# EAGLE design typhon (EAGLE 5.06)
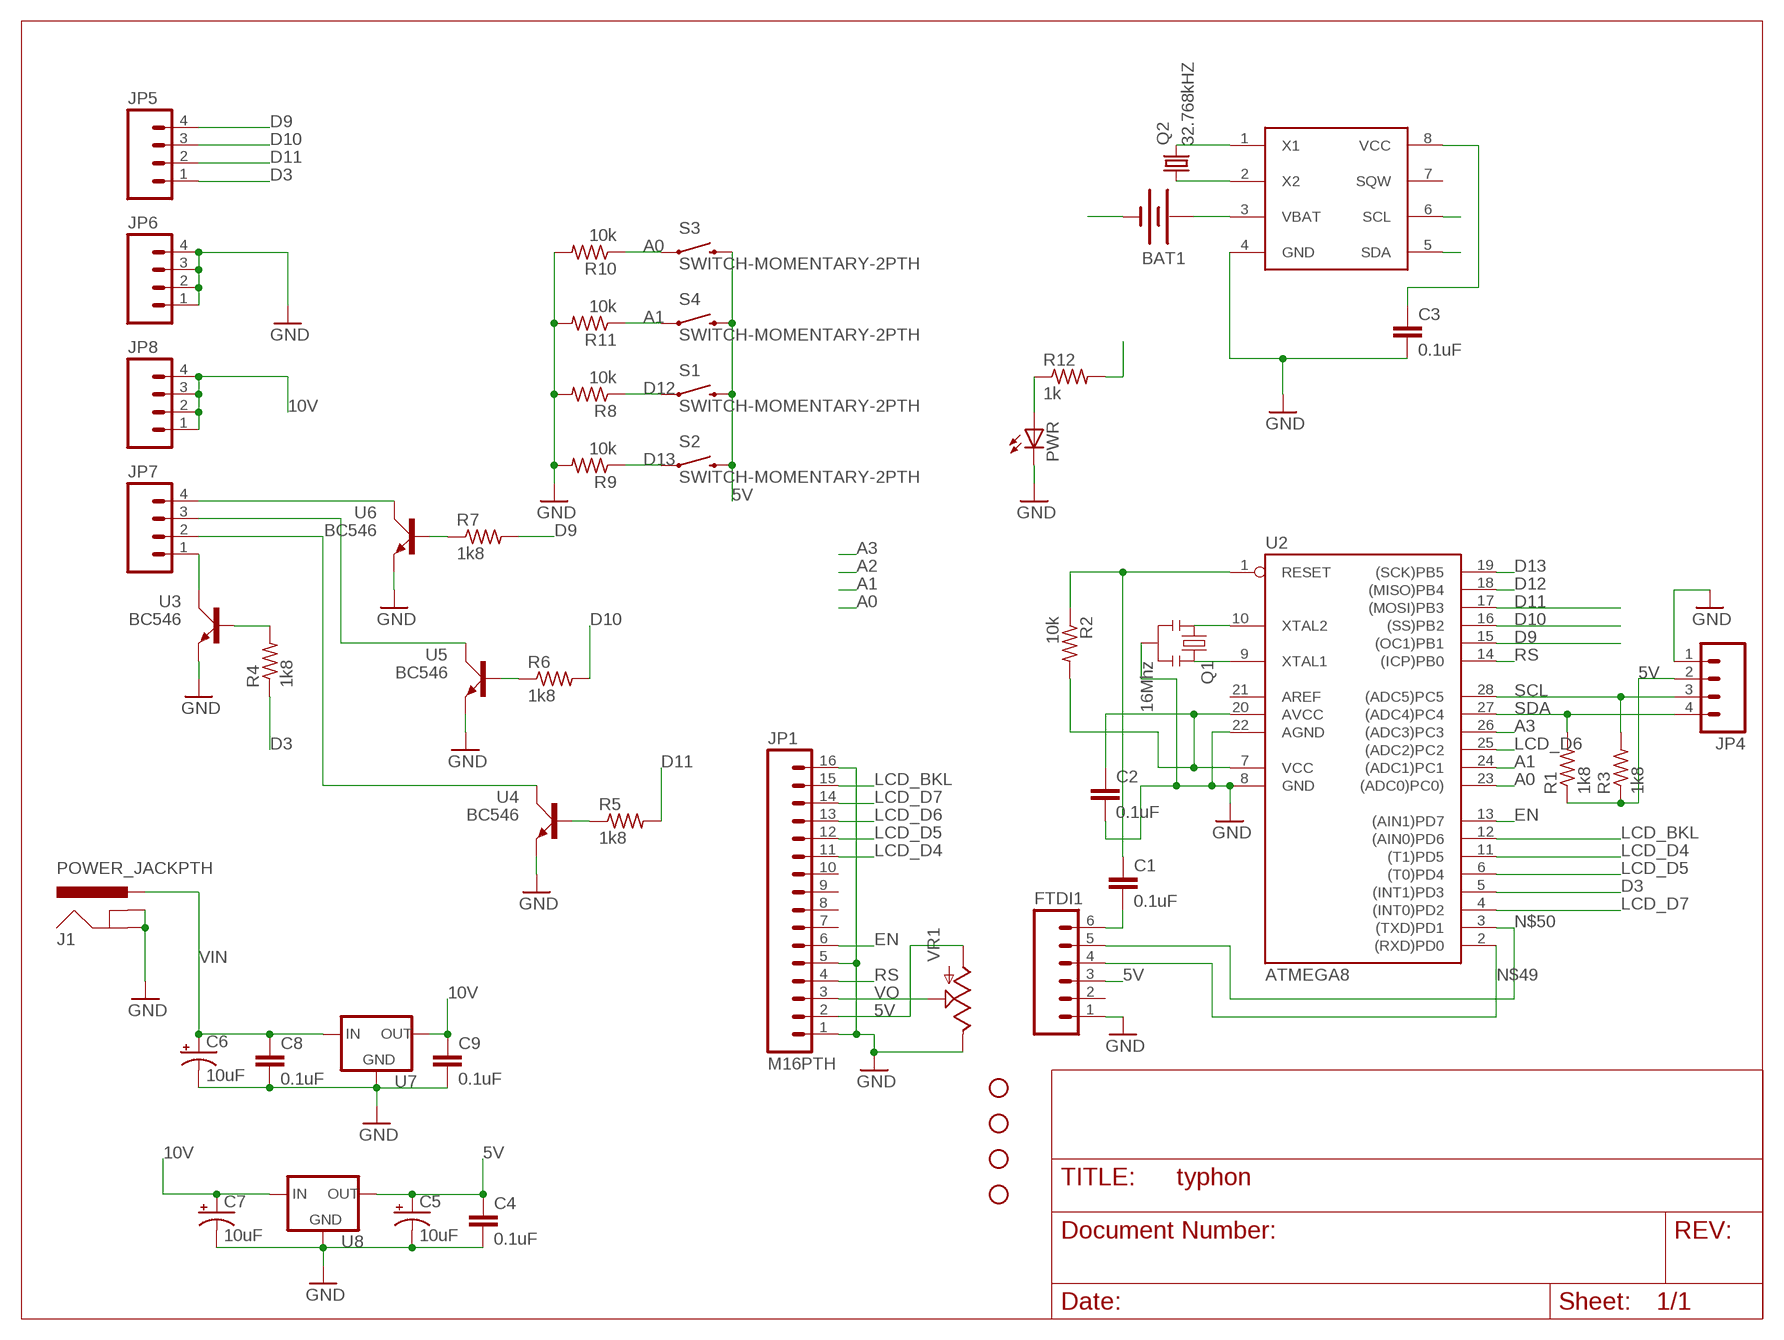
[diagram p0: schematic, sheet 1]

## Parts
BAT1  BATTERY12PTH_KEYSTONE  [BATT_12MM_KEYSTONE]
C1  0.1uF  CAPPTH  [CAP-PTH-SMALL]
C2  0.1uF  CAPPTH  [CAP-PTH-SMALL]
C3  0.1uF  CAPPTH  [CAP-PTH-SMALL]
C4  0.1uF  CAPPTH  [CAP-PTH-SMALL]
C5  10uF  CAP_POL6.3MMPTH  [CAP6.3MM2.5MM]
C6  10uF  CAP_POL6.3MMPTH  [CAP6.3MM2.5MM]
C7  10uF  CAP_POL6.3MMPTH  [CAP6.3MM2.5MM]
C8  0.1uF  CAPPTH  [CAP-PTH-SMALL]
C9  0.1uF  CAPPTH  [CAP-PTH-SMALL]
FTDI1  M06SIP  [1X06]
J1  POWER_JACKPTH  [POWER_JACK_PTH]
JP1  M16PTH  [1X16]
JP2  STAND-OFF  [STAND-OFF]
JP3  STAND-OFF  [STAND-OFF]
JP4  M04PTH  [1X04]
JP5  M04PTH  [1X04]
JP6  M04PTH  [1X04]
JP7  M04PTH  [1X04]
JP8  M04PTH  [1X04]
JP9  STAND-OFF  [STAND-OFF]
JP10  STAND-OFF  [STAND-OFF]
PWR  LED3MM  [LED3MM]
Q1  16Mhz  RESONATORPTH  [RESONATOR-PTH]
Q2  32.768kHZ  CRYSTALTC26H  [TC26H]
R1  1k8  R-US_0204/7  [0204/7]
R2  10k  R-US_0204/7  [0204/7]
R3  1k8  R-US_0204/7  [0204/7]
R4  1k8  R-US_0204/7  [0204/7]
R5  1k8  R-US_0204/7  [0204/7]
R6  1k8  R-US_0204/7  [0204/7]
R7  1k8  R-US_0204/7  [0204/7]
R8  10k  R-US_0204/7  [0204/7]
R9  10k  R-US_0204/7  [0204/7]
R10  10k  R-US_0204/7  [0204/7]
R11  10k  R-US_0204/7  [0204/7]
R12  1k  R-US_0204/7  [0204/7]
S1  SWITCH-MOMENTARY-2PTH  [TACTILE-PTH]
S2  SWITCH-MOMENTARY-2PTH  [TACTILE-PTH]
S3  SWITCH-MOMENTARY-2PTH  [TACTILE-PTH]
S4  SWITCH-MOMENTARY-2PTH  [TACTILE-PTH]
U1  DS1307DS1307  [DIP08]
U2  ATMEGA8  AT90S4433P  [DIL28-3]
U3  BC546  [TO92-]
U4  BC546  [TO92-]
U5  BC546  [TO92-]
U6  BC546  [TO92-]
U7  V_REG_78XX  [TO220AHV]
U8  V_REG_78XX  [TO220AHV]
VR1  POT  [TRIM_POT_SIDE]

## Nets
5V [Power]: C2.1 C3.1 C4.1 C5.P$2(+) FTDI1.3 JP1.2 JP4.2 R1.1 R2.2 R3.1 R12.2 S1.3 S2.3 S3.3 S4.3 U1.8(VCC) U2.7(VCC) U2.20(AVCC) U8.E(OUT) VR1.P$3(A)
10V [Power]: C7.P$2(+) C9.1 JP8.1 JP8.2 JP8.3 JP8.4 U7.E(OUT) U8.B(IN)
A0: R10.1 S3.1 U2.23((ADC0)PC0))
A1: R11.1 S4.1 U2.24((ADC1)PC1)
A3: U2.26((ADC3)PC3)
D3: JP5.1 R4.1 U2.5((INT1)PD3)
D9: JP5.4 R7.2 U2.15((OC1)PB1)
D10: JP5.3 R6.2 U2.16((SS)PB2)
D11: JP5.2 R5.2 U2.17((MOSI)PB3)
D12: R8.1 S1.1 U2.18((MISO)PB4)
D13: R9.1 S2.1 U2.19((SCK)PB5)
EN: JP1.6 U2.13((AIN1)PD7)
GND [Power]: BAT1.GND(-) C2.2 C3.2 C4.2 C5.P$1(-) C6.P$1(-) C7.P$1(-) C8.2 C9.2 FTDI1.1 J1.GND J1.GNDBREAK JP1.1 JP1.5 JP1.16 JP4.1 JP6.1 JP6.2 JP6.3 JP6.4 PWR.K(C) Q1.2 R8.2 R9.2 R10.2 R11.2 U1.4(GND) U2.8(GND) U2.22(AGND) U3.3(E) U4.3(E) U5.3(E) U6.3(E) U7.C(GND) U8.C(GND) VR1.P$1(E)
LCD_BKL: JP1.15 U2.12((AIN0)PD6)
LCD_D4: JP1.11 U2.11((T1)PD5)
LCD_D5: JP1.12 U2.6((T0)PD4)
LCD_D6: JP1.13 U2.25((ADC2)PC2)
LCD_D7: JP1.14 U2.4((INT0)PD2)
N$1: Q2.1 U1.2(X2)
N$2: Q2.2 U1.1(X1)
N$3: BAT1.V+(+) U1.3(VBAT)
N$4: PWR.A R12.1
N$5: JP7.1 U3.1(C)
N$6: R4.2 U3.2(B)
N$9: C1.1 R2.1 U2.1(RESET)
N$18: R7.1 U6.2(B)
N$19: JP7.4 U6.1(C)
N$20: R5.1 U4.2(B)
N$21: R6.1 U5.2(B)
N$22: JP7.3 U5.1(C)
N$23: JP7.2 U4.1(C)
N$36: Q1.3 U2.9(XTAL1)
N$38: Q1.1 U2.10(XTAL2)
N$49: FTDI1.4 U2.2((RXD)PD0)
N$50: FTDI1.5 U2.3((TXD)PD1)
N$51: C1.2 FTDI1.6
RS: JP1.4 U2.14((ICP)PB0)
SCL: JP4.3 R3.2 U1.6(SCL) U2.28((ADC5)PC5)
SDA: JP4.4 R1.2 U1.5(SDA) U2.27((ADC4)PC4)
VIN [Power]: C6.P$2(+) C8.1 J1.PWR U7.B(IN)
VO: JP1.3 VR1.P$2(S)
Unconnected: FTDI1.2 JP1.7 JP1.8 JP1.9 JP1.10 U1.7(SQW) U2.21(AREF)

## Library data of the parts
BAT1 = _allyourbase:BATTERY: Battery Holders
C1-C4 C8 C9 = _allyourbase:CAP: Capacitor
C5-C7 = _allyourbase:CAP_POL: Capacitor Polarized
FTDI1 = _allyourbase:M06: Header 6 Standard 6-pin 0.1" header. Use with straight break away headers (SKU : PRT-00116), right angle break away headers (PRT-00553), swiss pins (PRT-00743), machine pins (PRT-00117), and female headers (PRT-00115). Molex polarized connector foot print use with SKU : PRT-08094 with associated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
J1 = _allyourbase:POWER_JACK: Power Jack This is the standard 5.5mm barrel jack for power. The PTH is the most common, proven, reliable, footprint. All others are experimental. The Slot footprint only works if the mill layer is transmitted to the PCB fab house so be warned. Spark Fun Electronics SKU : PRT-00119. Mating wall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
JP1 = _allyourbase:M16
JP2 JP3 JP9 JP10 = _allyourbase:STAND-OFF: Stand Off
JP4-JP8 = _allyourbase:M04: Header 4 Standard 4-pin 0.1" header. Use with straight break away headers (SKU : PRT-00116), right angle break away headers (PRT-00553), swiss pins (PRT-00743), machine pins (PRT-00117), and female headers (PRT-00115). Molex polarized connector foot print use with SKU : PRT-08231 with associated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
PWR = _allyourbase:LED: LEDs
Q1 = _allyourbase:RESONATOR: Resonator Small SMD resonator. This is the itty bitty 10/20MHz resonators with built in caps. CSTCE10M0G55 and CSTCE20M0V53. Footprint has been reviewed closely but hasn't been tested yet.
Q2 = _allyourbase:CRYSTAL: CRYSTAL
R1-R12 = _allyourbase:R-US_: RESISTOR, American symbol
S1-S4 = _allyourbase:SWITCH-MOMENTARY-2
U1 = _allyourbase:DS1307
U2 = atmel:AT90S4433: MICROCONTROLLER 4 Kbytes FLASH 128 bytes SRAM 256 bytes EEPROM UART 6-channel 10 bit ADC
U3-U6 = _allyourbase:BC546
U7 U8 = _allyourbase:V_REG_78XX: Voltage Regulator Standard 7805 5V regulator. IGO (Input Ground Output). Spark Fun Electronics SKU : COM-00107
VR1 = _allyourbase:POT

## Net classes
0 default: width 0.254 mm, drill 0.508 mm
1 Power: width 0.305 mm, drill 0.508 mm

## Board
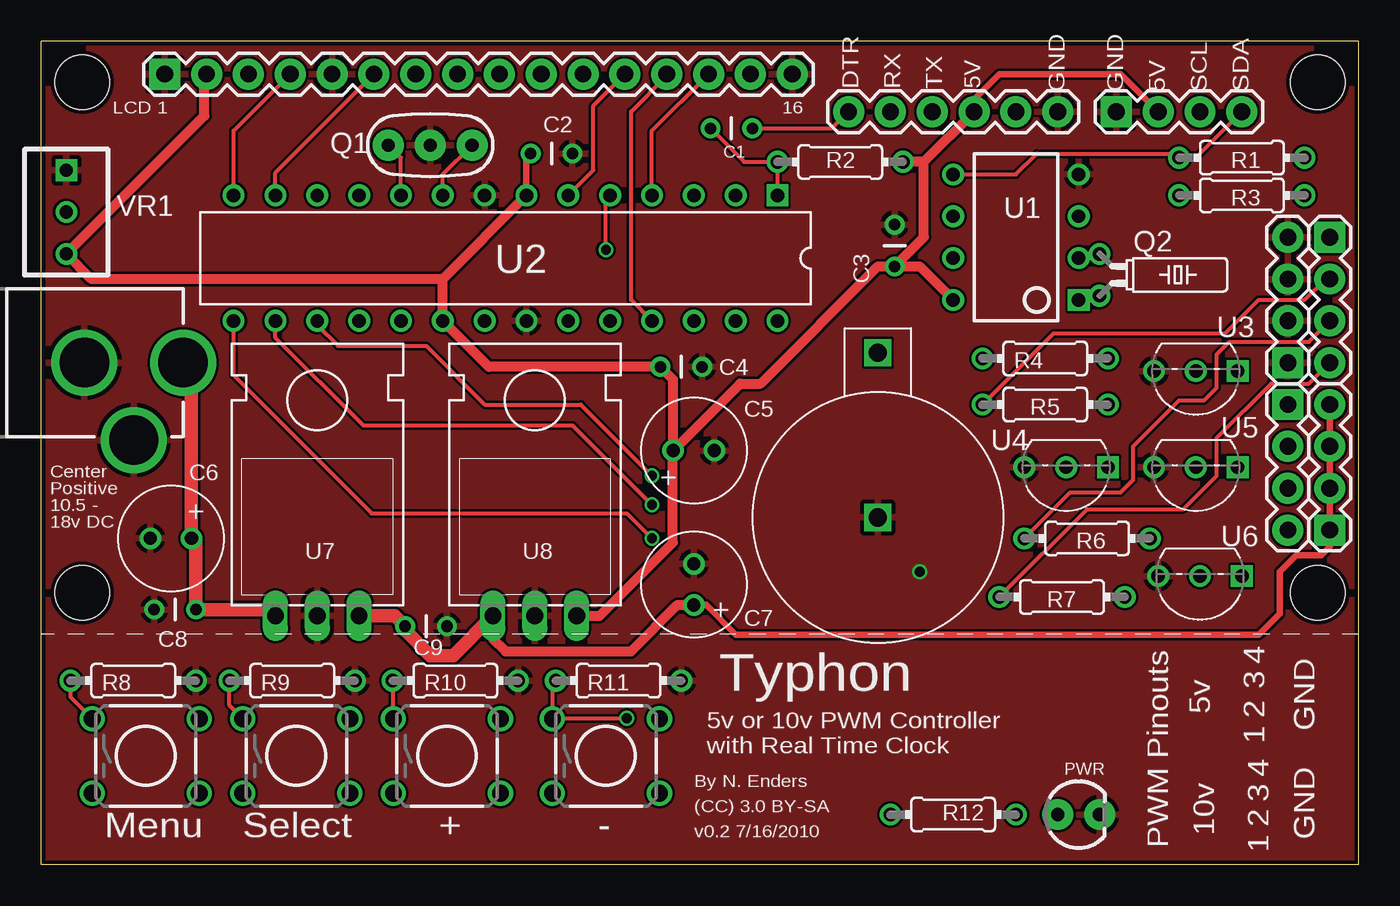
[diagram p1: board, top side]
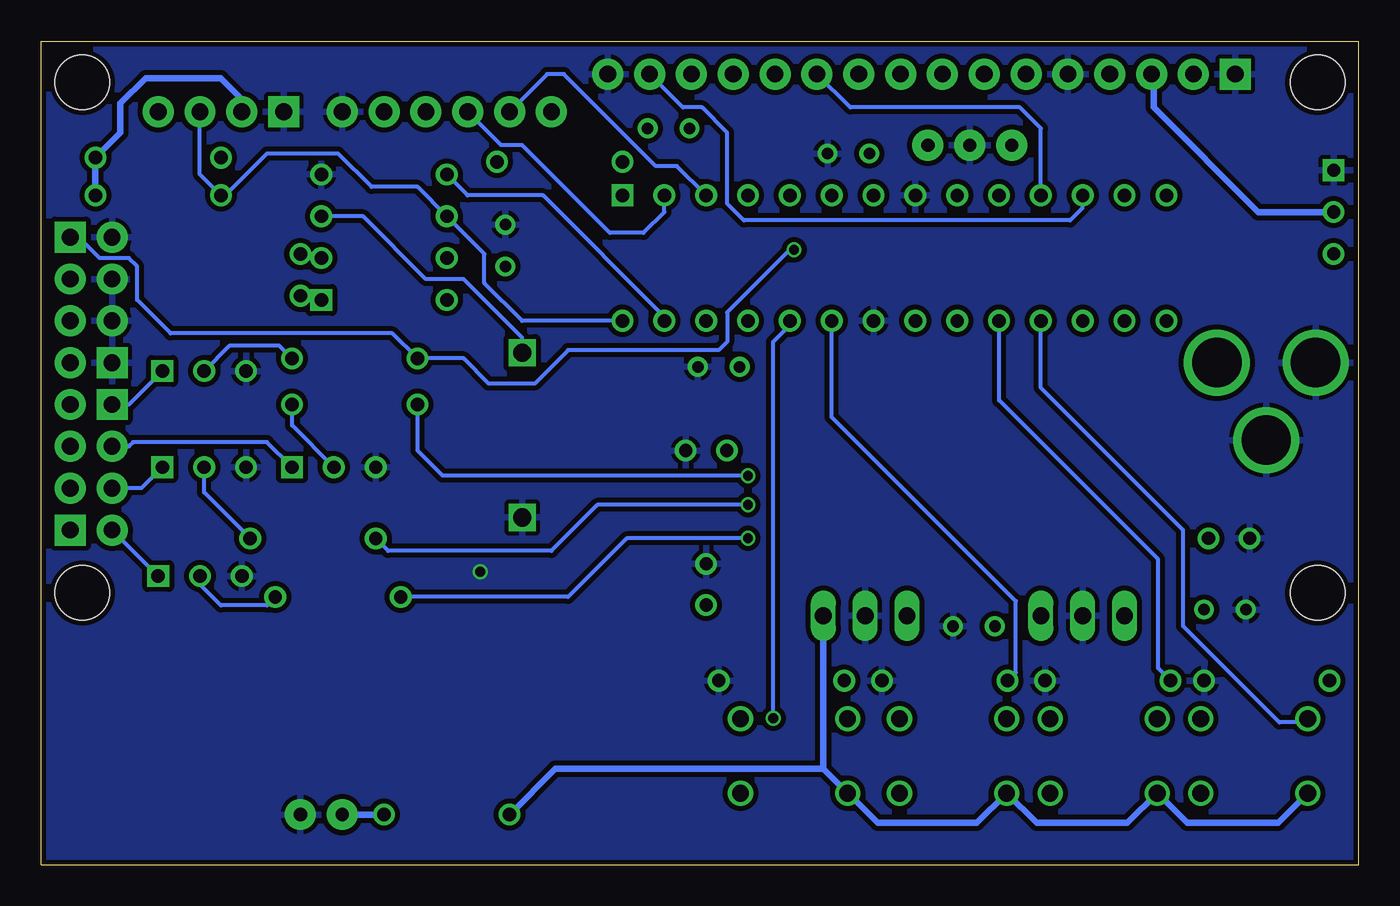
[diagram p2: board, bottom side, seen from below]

Size 80 x 50 mm. Coordinates in mm from the lower left corner, seen from the top.
Outline: 80,0 0,0 0,50 80,50 80,0
Copper layers (1*16): Top 0.035mm / dielectric 1.5mm / Bottom 0.035mm
Design rules "Fusion_eagle_rule_v1.1": minimum track width 6mil, minimum drill 12mil, track to track 6mil, track to pad 6mil, pad to pad 6mil, via to via 6mil, smd to smd 0mil, copper to edge 10mil, drill to drill 10mil, minimum pad ring 10mil, minimum via ring 6mil, stop-mask expansion 2mil, vias tented up to drill 100mil, thermal gap 10mil

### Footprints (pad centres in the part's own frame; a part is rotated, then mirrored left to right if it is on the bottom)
BATT_12MM_KEYSTONE = drill 1.1 square: GND 0,0; V+ 10,0
CAP-PTH-SMALL = drill 0.7 round: 1 0,0; 2 2.54,0
CAP6.3MM2.5MM = drill 0.8 round: P$1 -1.25,0; P$2 1.25,0
1X06 = drill 1.016 pad 1.88 round: 1 0,0; 2 2.54,0; 3 5.08,0; 4 7.62,0; 5 10.16,0; 6 12.7,0
POWER_JACK_PTH = drill 2.997 round: GND 0,7.7; GNDBREAK 4.7,10.7; PWR 0,13.7
1X16 = drill 1.016 pad 1.88 square: 1 0,0 | drill 1.016 pad 1.88 round: 2 2.54,0; 3 5.08,0; 4 7.62,0; 5 10.16,0; 6 12.7,0; 7 15.24,0; 8 17.78,0; 9 20.32,0; 10 22.86,0; 11 25.4,0; 12 27.94,0; 13 30.48,0; 14 33.02,0; 15 35.56,0; 16 38.1,0
STAND-OFF = hole 3.302: 0,0
1X04 = drill 1.016 pad 1.88 square: 1 0,0 | drill 1.016 pad 1.88 round: 2 2.54,0; 3 5.08,0; 4 7.62,0
LED3MM = drill 0.813 pad 1.88 round: A -1.27,0; K 1.27,0
RESONATOR-PTH = drill 0.8 pad 1.88 round: 1 -2.54,0; 2 0,0; 3 2.54,0
TC26H = drill 0.813 round: 1 -1.27,0; 2 1.27,0
0204/7 = drill 0.813 round: 1 -3.81,0; 2 3.81,0
TACTILE-PTH = drill 1.016 round: 1 -3.251,2.261; 2 3.251,2.261; 3 -3.251,-2.261; 4 3.251,-2.261
DIP08 = drill 0.813 square: 1 -3.81,-3.81 | drill 0.813 round: 2 -1.27,-3.81; 3 1.27,-3.81; 4 3.81,-3.81; 5 3.81,3.81; 6 1.27,3.81; 7 -1.27,3.81; 8 -3.81,3.81
DIL28-3 = drill 0.813 square: 1 -16.51,-3.81 | drill 0.813 round: 2 -13.97,-3.81; 3 -11.43,-3.81; 4 -8.89,-3.81; 5 -6.35,-3.81; 6 -3.81,-3.81; 7 -1.27,-3.81; 8 1.27,-3.81; 9 3.81,-3.81; 10 6.35,-3.81; 11 8.89,-3.81; 12 11.43,-3.81; 13 13.97,-3.81; 14 16.51,-3.81; 15 16.51,3.81; 16 13.97,3.81; 17 11.43,3.81; 18 8.89,3.81; 19 6.35,3.81; 20 3.81,3.81; 21 1.27,3.81; 22 -1.27,3.81; 23 -3.81,3.81; 24 -6.35,3.81; 25 -8.89,3.81; 26 -11.43,3.81; 27 -13.97,3.81; 28 -16.51,3.81
TO92- = drill 0.813 square: 1 -2.54,0 | drill 0.813 round: 2 0,0; 3 2.54,0
TO220AHV = drill 1.016 long: B -2.54,-1.905; C 0,-1.905; E 2.54,-1.905
TRIM_POT_SIDE = drill 0.8 square: P$1 0,2.54 | drill 0.8 round: P$2 0,0; P$3 0,-2.54

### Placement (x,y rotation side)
BAT1  50.8,21.08 90 top
C1  40.64,44.7 0 top
C2  29.72,43.18 0 top
C3  51.82,36.32 90 top
C4  37.59,30.23 0 top
C5  39.62,25.15 180 top
C6  7.87,19.81 0 top
C7  39.62,17.02 270 top
C8  9.4,15.49 180 top
C9  22.1,14.48 0 top
FTDI1  61.72,45.72 180 top
J1  -5.08,30.48 270 top
JP1  7.5,48 0 top
JP2  2.5,47.5 0 top
JP3  77.5,47.5 0 top
JP4  65.28,45.72 0 top
JP5  78.23,38.1 270 top
JP6  75.69,30.48 90 top
JP7  75.69,27.94 270 top
JP8  78.23,20.32 90 top
JP9  2.5,16.5 0 top
JP10  77.5,16.5 0 top
PWR  62.99,3.05 0 top
Q1  23.62,43.69 0 top
Q2  64.26,35.81 270 top
R1  72.9,42.93 180 top
R2  48.51,42.67 0 top
R3  72.9,40.64 180 top
R4  60.96,30.73 0 top
R5  60.96,27.94 180 top
R6  63.5,19.81 180 top
R7  61.98,16.26 180 top
R8  5.59,11.18 0 top
R9  15.24,11.18 0 top
R10  25.15,11.18 0 top
R11  35.05,11.18 0 top
R12  55.37,3.05 180 top
S1  6.35,6.6 0 top
S2  15.49,6.6 0 top
S3  24.64,6.6 0 top
S4  34.29,6.6 0 top
U1  59.18,38.1 90 top
U2  28.19,36.83 180 top
U3  70.1,29.97 180 top
U4  62.23,24.13 180 top
U5  70.1,24.13 180 top
U6  70.36,17.53 180 top
U7  16.76,17.02 0 top
U8  29.97,17.02 0 top
VR1  1.52,39.62 0 top

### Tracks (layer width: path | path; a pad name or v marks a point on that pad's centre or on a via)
5V
  Top 0.406: U2.7 29.46,42.93 C2.1 | 9.91,47.87 JP1.2 | FTDI1.3 56.64,46.48 58.17,48.01 65.53,48.01 JP4.2 | 38.35,25.13 C5.P$2
  Top 0.61: 24.38,35.56 U2.20 27.18,30.23 C4.1 38.37,29.44 C5.P$2 42.44,29.21 43.69,29.21 50.8,36.32 C3.1 | 24.38,35.56 U2.7 | 24.38,35.56 3.05,35.56 VR1.P$3 9.91,45.47 9.91,47.87 | 53.59,42.67 R2.2 | 53.59,42.67 FTDI1.3 | U8.E 33.91,15.11 38.35,19.56 38.35,25.13 | U1.8 53.34,36.32 C3.1 | 53.59,42.67 53.59,38.1 C3.1
  Bottom 0.406: 32.51,5.82 U8.E | 32.51,5.82 S4.3 31.01,4.34 29.21,2.54 23.19,2.54 S3.3 21.36,4.34 19.56,2.54 14.05,2.54 S2.3 12.22,4.34 10.41,2.54 4.9,2.54 S1.3 | R3.1 R1.1 75.18,44.45 75.18,46.23 73.66,47.75 69.09,47.75 67.82,46.48 JP4.2 | 32.51,5.82 48.79,5.82 R12.2
10V
  Top 0.406: C9.1 22.1,14.22 | JP8.4 JP8.3 JP8.2 JP8.1 78.23,19.3 77.72,18.8 76.2,18.8 75.18,17.78 75.18,15.24 73.91,13.97 42.16,13.97 40.37,15.77 C7.P$2
  Top 0.61: U8.B 27.43,13.72 28.19,12.95 35.81,12.95 38.63,15.77 C7.P$2
  Top 0.813: U7.E 21.46,15.11 C9.1 | 22.1,14.22 23.62,12.7 25.02,12.7 U8.B
A0
  Top 0.254: S3.1 21.39,11.12 R10.1
  Bottom 0.254: U2.23 32,27.18 20.83,16 20.83,11.68 R10.1
A1  (via drill 0.6)
  Top 0.254: 31.06,8.89 v35.56,8.89 | S4.1 31.06,8.89 | 31.06,8.89 31.06,11 R11.1
  Bottom 0.254: U2.24 34.54,32.77 35.56,31.75 v35.56,8.89
D3  (via drill 0.6)
  Top 0.254: U2.5 34.29,40.39 v34.29,37.34
  Bottom 0.254: v34.29,37.34 34.54,37.34 38.35,33.53 38.35,31.75 38.86,31.24 48.01,31.24 50.04,29.21 52.83,29.21 54.36,30.73 R4.1 58.67,32.26 72.14,32.26 74.17,34.29 74.17,36.32 74.68,36.83 76.45,36.83 77.72,38.1 JP5.1
D9  (via drill 0.6)
  Top 0.254: U2.15 11.68,29.72 20.07,21.34 35.56,21.34 v37.08,19.81 | R7.2 63.5,21.59 69.34,21.59 71.37,23.62 71.37,25.91 74.68,29.21 76.96,29.21 JP5.4
  Bottom 0.254: v37.08,19.81 44.45,19.81 48.01,16.26 R7.2
D10  (via drill 0.6)
  Top 0.254: U2.16 14.22,32 19.56,26.67 32.26,26.67 v37.08,21.84 | R6.2 62.48,22.61 65.53,22.61 66.29,23.37 66.29,25.4 69.09,28.19 70.61,28.19 71.37,28.96 71.37,30.99 72.14,31.75 76.96,31.75 JP5.3
  Bottom 0.254: v37.08,21.84 46.23,21.84 49.02,19.05 58.93,19.05 R6.2
D11  (via drill 0.6)
  Top 0.254: U2.17 16.76,32.77 18.03,31.5 23.37,31.5 26.92,27.94 32.77,27.94 v37.08,23.62 | R5.2 61.47,32.26 71.88,32.26 73.91,34.29 76.71,34.29 77.98,35.56 JP5.2
  Bottom 0.254: v37.08,23.62 55.63,23.62 57.15,25.15 R5.2
D12
  Top 0.254: R8.1 1.78,10.19 S1.1
  Bottom 0.254: U2.18 19.3,28.96 10.67,20.32 10.67,14.48 4.83,8.64 3.33,8.64 S1.1
D13
  Top 0.254: R9.1 11.43,9.68 S2.1
  Bottom 0.254: U2.19 21.84,28.19 12.19,18.54 12.19,11.94 R9.1
EN
  Top 0.254: U2.13 14.22,42.02 JP1.6
GND  (via drill 0.6)
  other vias: 53.34,17.78
  pour Bottom (isolate 0.305): 0,50.04 80.01,50.04 80.01,0 0,0
  pour Top: 0,50.04 0,0 80.26,0 80.01,50.04
LCD_BKL
  Bottom 0.254: U2.12 16.76,39.88 17.53,39.12 37.34,39.12 38.35,40.13 38.35,44.45 39.88,45.97 41.03,45.97 JP1.15
LCD_D4
  Bottom 0.254: U2.11 19.3,44.7 20.57,45.97 30.87,45.97 JP1.11
LCD_D5
  Top 0.254: U2.6 33.53,42.16 33.53,46.09 JP1.12
LCD_D6
  Top 0.254: U2.25 35.81,34.29 35.81,45.72 37.98,47.89 JP1.13
LCD_D7
  Top 0.254: U2.4 37.08,44.56 JP1.14
N$1
  Top 0.305: Q2.1 63.25,37.08 U1.2
N$2
  Top 0.305: U1.1 64.01,34.29 Q2.2
N$3
  Bottom 0.254: BAT1.V+ 50.8,32 54.36,35.56 56.64,35.56 60.45,39.37 U1.3
N$4
  Bottom 0.406: R12.1 PWR.A
N$5
  Bottom 0.254: U3.1 74.68,27.94 JP7.1
N$6
  Bottom 0.254: U3.2 68.58,31.5 65.53,31.5 R4.2
N$9
  Top 0.254: U2.1 R2.1 42.67,42.67 C1.1
N$18
  Bottom 0.254: R7.1 66.29,15.75 69.09,15.75 70.36,17.02 U6.2
N$19
  Bottom 0.254: U6.1 JP7.4
N$20
  Bottom 0.254: U4.2 64.77,26.67 R5.1
N$21
  Bottom 0.254: R6.1 70.1,22.61 U5.2
N$22
  Bottom 0.254: U5.1 73.91,22.86 JP7.3
N$23
  Bottom 0.254: U4.1 66.29,25.65 74.42,25.65 74.68,25.4 JP7.2
N$36
  Top 0.254: U2.9 24.38,41.91 Q1.3
N$38
  Top 0.254: U2.10 21.84,42.93 Q1.1
N$49
  Bottom 0.254: U2.2 42.16,39.62 43.43,38.35 45.47,38.35 50.8,43.69 52.07,43.69 FTDI1.4
N$50
  Bottom 0.254: U2.3 41.4,42.42 42.67,42.42 48.26,48.01 49.28,48.01 FTDI1.5
N$51
  Top 0.254: C1.2 48.01,44.7 FTDI1.6
RS
  Top 0.254: U2.14 11.68,44.56 JP1.4
SCL
  Bottom 0.254: U2.28 50.8,33.02 53.09,35.31 53.09,37.08 U1.6 57.15,41.15 59.94,41.15 61.98,43.18 66.29,43.18 68.83,40.64 R3.2 70.36,41.91 JP4.3
SDA
  Top 0.254: U1.5 59.18,41.91 60.45,43.18 68.83,43.18 R1.2 70.1,42.93 JP4.4
  Bottom 0.254: U2.27 42.16,33.27 49.53,40.64 54.1,40.64 U1.5
VIN
  Top 0.813: U7.B 13.84,15.49 C8.1 9.4,19.54 C6.P$2 9.12,29.98 J1.PWR
VO
  Bottom 0.406: VR1.P$2 6.1,39.62 12.45,45.97 12.45,47.87 JP1.3

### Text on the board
tNames: DTR | RX | TX | 5V | GND | GND | 5V | SCL | SDA | LCD 1 | 16 | Center | Positive | 10.5 - | 18v DC | 4 | Typhon | 3 | 5v | 2 | 5v or 10v PWM Controller | GND | with Real Time Clock | 1 | By N. Enders | 4 | 3 | (CC) 3.0 BY-SA | Menu | Select | + | - | v0.2 7/16/2010 | 10v | 2 | GND | PWM Pinouts | 1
